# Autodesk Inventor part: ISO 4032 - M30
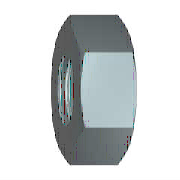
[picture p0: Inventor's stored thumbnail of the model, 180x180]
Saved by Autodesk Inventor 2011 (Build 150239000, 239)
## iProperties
IsCustomPart: 0
Created: 2009-02
Part Number: ISO 4032 - M30
Material: Stainless Steel, 440C
Description: Hexagon nuts, style 1 - Product grades A and B
Document SubType Name: Modeling
Standard: ISO 4032
Designer: "initialen"
Standard Revision: Third edition 1999-08-15
Standards Organization: ISO
Language: en-US
Size Designation: M30
Categories: <MemberInstance><Categories><Category DisplayName="Fasteners" InternalName="e4da775c-781d-43d5-af7c-5136215cf5a6" Mnemonic="FSTN"><Category DisplayName="Nuts" I
Density: 7.75 g/cm^3
Mass: 249.433 g
Surface Area: 82.479 cm^2
Volume: 32.1849 cm^3
Author: "initialen"
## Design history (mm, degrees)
body "Solid1"
workaxis "Work Axis1"
workplane "Work Plane1"
sketch "Sketch1"
  geometry: L1 (-26.558, 0)-(-13.279, 23); L2 (-13.279, 23)-(13.279, 23); L3 (13.279, 23)-(26.558, 0); L4 (26.558, 0)-(13.279, -23); L5 (13.279, -23)-(-13.279, -23); L6 (-13.279, -23)-(-26.558, 0); 2 further points
  constraints: 12 end point, 1 coincident, 1 horizontal, 11 other
  dimensions: "d0" = 53.11622 distance of L3.end L1.start (= 1.1547 x SW)
extrude "Body" new body sketch "Sketch1" distance "d1" = 25.6 (= KOH); taper "d2" = 0 deg
revolve "Chamfer1" stored, may be unused: angle "d7" = 90 deg
sketch "Sketch3"
  geometry: 4 further points
  constraints: 1 coincident, 1 other
hole "Thread" sketch "Sketch3" diameter "d25" = 26.211; stored, may be unused: countersink angle "d29" = 82 deg, drill point angle "d31" = 118 deg; dims "d26" = 6, "d27" = 4, "d28" = 2, "d30" = 8
chamfer "Chamfer2" distance "d8" = 1.89443 (= -0.5 x GD1 + 0.5 x NND); stored, may be unused: angle "d9" = 30 deg, second distance "d40" = 1.89443 (= -0.5 x GD1 + 0.5 x NND)
chamfer "Chamfer3" distance "d10" = 1.89443 (= -0.5 x GD1 + 0.5 x NND); stored, may be unused: angle "d11" = 30 deg, second distance "d41" = 1.89443 (= -0.5 x GD1 + 0.5 x NND)
sketch "Sketch2"
  geometry: L1 (0, 13.279)-(0, 26.558) reference; L2 (0, 26.558)-(25.6, 26.558) reference; L3 (25.6, 13.279)-(25.6, 26.558) reference; L4 (-5.12, 0)-(30.72, 0) reference; L5 (2.978, 26.558)-(0, 21.4); L6 (22.622, 26.558)-(25.6, 21.4)
  constraints: 4 end point, 4 point on line
  dimensions: "d3" = 30 deg angle of L1 L5 (= ANG1); "d4" = 30 deg angle of L3 L6 (= ANG2); "d5" = 42.8 diameter of L5.end L4 (= SW0); "d6" = 42.8 diameter of L6.end L4 (= SW01)
other parameters: "ANG1" = 30 deg [user parameter; used in 1 equation term], "ANG2" = 30 deg [user parameter; used in 1 equation term], "KOH" = 25.6 [user parameter; used in 1 equation term], "SW" = 46 [user parameter; used in 2 equation terms], "SW0" = 42.8 [user parameter; used in 2 equation terms], "SW01" = 42.8 (= SW0) [user parameter; used in 1 equation term], "GD1" = 26.21114 (computed from THREADDIA, PTC, TOA) [user parameter; used in 4 equation terms], "d13" = 0, "d14" = 0, "d39" = 0, "d42" = 0, "GUL" = 1.89443 (= 0.541266 x PTC) [user parameter], "TPU" = 2.85714 (computed from PTC) [user parameter], "TOA" = 30 deg [user parameter; used in 1 equation term], "PTC" = 3.5 [user parameter; used in 4 equation terms], "E0" = 53.13 (= 1.155 x SW) [user parameter], "GAL" = 1.89443 (= 0.541266 x PTC) [user parameter]
